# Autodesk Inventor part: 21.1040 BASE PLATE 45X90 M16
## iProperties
Created: 2007-03
Part Number: 21.1040 BASE PLATE 45X90 M16
Document SubType Name: Modeling
Designer: Andy Moles
Material: Aluminum-6061
Mass: 142.455 g
Surface Area: 148.17 cm^2
Volume: 52.5665 cm^3
Density: 2.71 g/cm^3
Author: Andy Moles
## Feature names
1. Extrusion1
2. Hole1
3. Hole2
4. Fillet1
5. Revolution1
6. Fillet2
